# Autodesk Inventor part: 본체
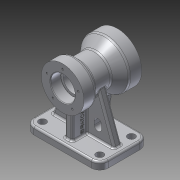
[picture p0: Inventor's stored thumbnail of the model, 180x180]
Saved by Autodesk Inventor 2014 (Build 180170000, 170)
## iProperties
Created: 2015-08
Part Number: 본체
Material: 알루미늄 6061
Document SubType Name: Modeling
Designer: USER
Density: 2.71 g/cm^3
Appearance: 알루미늄 - 평지
Mass: 1062.8 g
Surface Area: 749.64 cm^2
Volume: 392.179 cm^3
Author: USER
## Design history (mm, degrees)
sketch "스케치1"
  geometry: L1 (-61, 40)-(61, 40); L2 (61, 40)-(61, -40); L3 (61, -40)-(-61, -40); L4 (-61, -40)-(-61, 40); L5 (-61, 40)-(61, -40); 2 further points
  constraints: 10 end point, 2 coincident, 2 parallel, 1 horizontal, 1 midpoint, 1 perpendicular
  dimensions: "d0" = 122 distance of L1.start L1.end; "d1" = 80 distance of L1.end L2.end
extrude "돌출1" new body sketch "스케치1" distance "d2" = 12; taper "d3" = 0 deg
sketch "스케치2"
  geometry: L1 (50, 90)-(-40, 90); L2 (50, 90)-(50, 130); L3 (50, 130)-(30, 130); L4 (30, 130)-(13.315, 116); L5 (13.315, 116)-(-14.804, 116); L6 (-14.804, 116)-(-20, 125); L7 (-20, 125)-(-40, 125); L8 (-40, 125)-(-40, 90); 2 further points
  constraints: 16 end point, 3 parallel, 2 perpendicular, 1 horizontal, 1 vertical alignment
  dimensions: "d4" = 90 distance of L1.start L1.end; "d5" = 90 distance from line of point (0, 0) L1; "d6" = 80 diameter of L3 L1; "d7" = 52 diameter of L5 L1; "d8" = 70 diameter of L7 L1; "d9" = 20 distance from line of L6.end L8; "d10" = 20 distance from line of L3.end L2; "d11" = 60 deg angle of L6 L5; "d12" = 40 deg angle of L4 L5
revolve "회전1" sketch "스케치2" stored, may be unused: angle "d13" = 90 deg
sketch "스케치3"
  geometry: C1 r 35 at (0, 0) reference; C2 r 20 at (0, 0); 1 further point
  constraints: 1 centre point, 1 coincident
  dimensions: "d14" = 40 diameter of C2
extrude "돌출2" cut sketch "스케치3" distance "d15" = 17; taper "d16" = 0 deg
sketch "스케치4"
  geometry: C1 r 40 at (0, 0) reference; C2 r 26 at (0, 0); 1 further point
  constraints: 1 centre point, 1 coincident
  dimensions: "d17" = 52 diameter of C2
extrude "돌출3" cut sketch "스케치4" distance "d18" = 20; taper "d19" = 0 deg
sketch "스케치5"
  geometry: C1 r 26 at (0, 0) reference; C2 r 19 at (0, 0); 1 further point
  constraints: 1 centre point, 1 coincident
  dimensions: "d20" = 38 diameter of C2
extrude "돌출4" cut sketch "스케치5" distance "d21" = 3; taper "d22" = 0 deg
sketch "스케치6"
  geometry: C1 r 20 at (0, 0) reference; C2 r 16 at (0, 0); 1 further point
  constraints: 1 centre point, 1 coincident
  dimensions: "d23" = 32 diameter of C2
extrude "돌출5" cut sketch "스케치6" stored distance "d24" = 3; taper "d25" = 0 deg
sketch "스케치7"
  geometry: L1 (61, 12)-(-61, 12) reference; L2 (-51, 12)-(-25.091, 83.185); L3 (51, 12)-(25.091, 83.185); L4 (61, 0)-(61, 12) reference; L5 (-61, 0)-(-61, 12) reference; A1 r 26 centre (0, 90) between (-25.091, 83.185) and (25.091, 83.185) reference; 1 further point
  constraints: 4 end point, 2 point on circle, 2 point on line
  dimensions: "d26" = 10 distance from line of L4 L3.start; "d27" = 10 distance from line of L5 L2.start; "d28" = 70 deg angle of L1 L2; "d29" = 70 deg angle of L1 L3
extrude "돌출6" join sketch "스케치7" stored distance "d30" = 12; taper "d31" = 0 deg
sketch "스케치8"
  geometry: L1 (40, 12)-(-40, 12) reference; L2 (-40, 55)-(-20, 55) reference; L3 (-20, 55)-(-14.804, 64) reference; L4 (-14.804, 64)-(13.315, 64) reference; L5 (13.315, 64)-(30, 50) reference; L6 (30, 50)-(50, 50) reference; L7 (-30, 12)-(-30, 55); L8 (30, 12)-(36.7, 50); L9 (-40, 0)-(-40, 12) reference; L10 (40, 0)-(40, 12) reference; 1 further point
  constraints: 4 end point, 3 point on line, 1 midpoint, 1 perpendicular
  dimensions: "d32" = 10 distance between parallel lines of L9 L7; "d33" = 10 distance from line of L10 L8.start; "d34" = 80 deg angle of L1 L8
feature "리브1" dims "d35" = 1, "d36" = 6, "d37" = 0, "d38" = 0, "d39" = 1, "d40" = 1
feature "리브2" dims "d41" = 1, "d42" = 6, "d43" = 0, "d44" = 0, "d45" = 1, "d46" = 1
feature "리브3" dims "d47" = 1, "d48" = 6, "d49" = 0, "d50" = 0, "d51" = 1, "d52" = 1
feature "리브4" dims "d53" = 1, "d54" = 6, "d55" = 0, "d56" = 0, "d57" = 1, "d58" = 1
sketch "스케치9"
  geometry: L1 (6, 64.702)-(6, 12) reference; L2 (51, 12)-(6, 12) reference; L3 (24, 30)-(24, 36); L4 (18, 30)-(18, 36); L5 (30, 36)-(30, 30); L6 (61, 0)-(61, 12) reference; A1 r 6 centre (24, 30) between (18, 30) and (30, 30); A2 r 6 centre (24, 36) between (30, 36) and (18, 36); 2 further points
  constraints: 8 end point, 4 point on circle, 4 tangent, 2 centre point, 2 parallel, 1 midpoint
  dimensions: "d59" = 12 distance between parallel lines of L4 L5; "d60" = 18 dimension on A1 A2; "d61" = 37 distance from line of L6 point (24, 33); "d62" = 18 distance from line of L3.start L2
extrude "돌출7" cut sketch "스케치9" distance "d63" = 12; taper "d64" = 0 deg
sketch "스케치10"
  geometry: L1 (61, 40)-(-61, 40) reference; L2 (-61, 40)-(-61, -40) reference; C1 r 6 at (-47, 26); C2 r 6 at (-47, -26); C3 r 6 at (47, -26); C4 r 6 at (47, 26); 1 further point
  constraints: 4 centre point, 2 horizontal alignment, 2 vertical alignment
  dimensions: "d65" = 12 diameter of C1; "d66" = 12 diameter of C2; "d67" = 12 diameter of C3; "d68" = 12 diameter of C4; "d69" = 94 distance of C4.centre C1.centre; "d70" = 52 distance of C3.centre C4.centre; "d71" = 14 distance from line of L2 C1.centre; "d72" = 14 distance from line of L1 C4.centre
extrude "돌출8" cut sketch "스케치10" distance "d73" = 12; taper "d74" = 0 deg
sketch "스케치11" dims "d75" = 54
  geometry: C1 r 20 at (0, 0) reference; C2 r 35 at (0, 0) reference; 3 further points
  constraints: 2 vertical alignment, 1 coincident, 2 other
hole "구멍1" sketch "스케치11" at (0, 27) diameter "d76" = 3.242; stored, may be unused: countersink angle "d80" = 90 deg, drill point angle "d82" = 118 deg; dims "d77" = 10, "d78" = 4, "d79" = 2, "d81" = 13
sketch "스케치12" dims "d86" = 66
  geometry: C1 r 26 at (0, 0) reference; 3 further points
  constraints: 2 vertical alignment, 1 coincident, 2 other
hole "구멍2" sketch "스케치12" at (0, -33) diameter "d87" = 3.242; stored, may be unused: countersink angle "d91" = 90 deg, drill point angle "d93" = 118 deg; dims "d88" = 10, "d89" = 4, "d90" = 2, "d92" = 13
chamfer "모따기1" distance "d97" = 1; stored, may be unused: second distance "d98" = 2, angle "d99" = 45 deg
fillet "모깎기1" dims "d100" = 3
fillet "모깎기2" dims "d101" = 3
fillet "모깎기3" dims "d102" = 14
fillet "모깎기4" dims "d103" = 3
fillet "모깎기5" dims "d104" = 3
fillet "모깎기6" dims "d105" = 5
fillet "모깎기7" dims "d106" = 0.3
fillet "모깎기8" dims "d107" = 3
sketch "스케치13"
  geometry: L1 (3, 53)-(3, 1) reference; L2 (-37.119, -3)-(0, -3) reference; 2 further points
  constraints: 1 other
  dimensions: "d108" = 24 distance from line of L1 point (-21, 13); "d109" = 16 distance from line of point (-21, 13) L2
feature "엠보싱1" sketch "스케치13" dims "d0" = 122, "d1" = 80, "d110" = 0.5, "d111" = 0
node "솔리드1"
mirror "대칭1"
pattern_circular "원형 패턴1" dims angle "d84" = 360 deg
pattern_circular "원형 패턴2" dims angle "d95" = 360 deg
